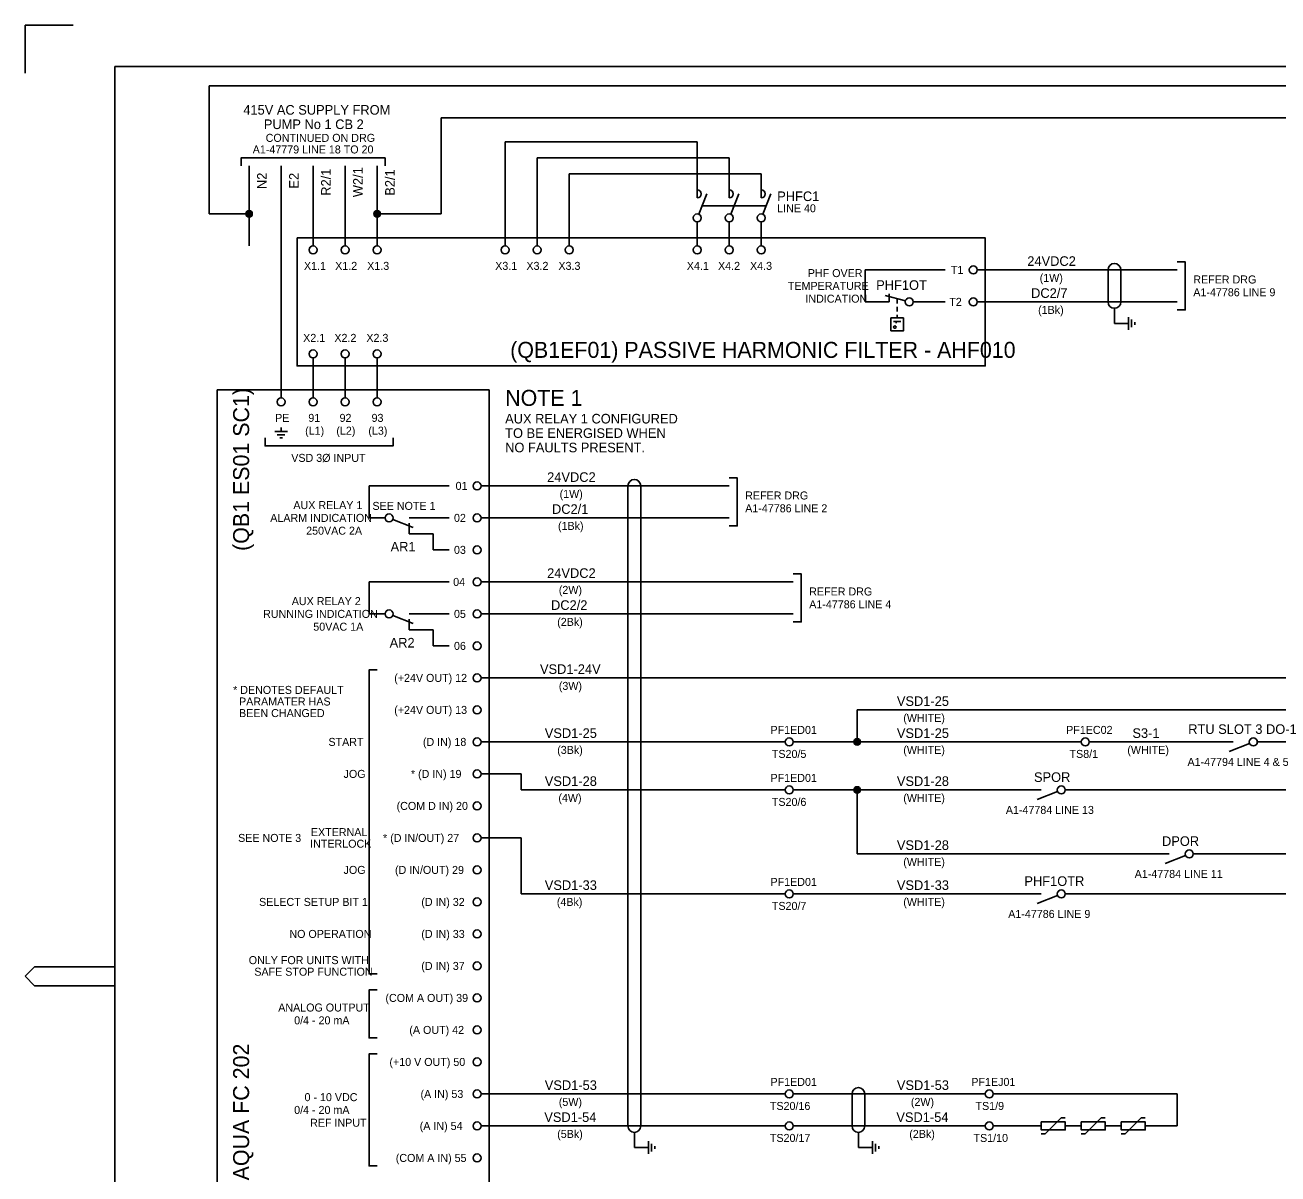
# Model space of a CAD drawing. Extents: x 0 to 841, y 0 to 594.
# Drawn here: x 0 to 391.4, y 235 to 594 of the extents above; entities that cross this region are included whole.
import ezdxf

# ---------------------------------------------------------------- set-up
doc = ezdxf.new("R2010")
doc.units = 0
for name, color, linetype in [('A1BORDER', 7, 'Continuous'), ('BASE', 7, 'Continuous'), ('Level 1', 7, 'Continuous'), ('Level 10', 7, 'Continuous'), ('Level 4', 7, 'Continuous'), ('Level 5', 7, 'Continuous'), ('Level 6', 7, 'Continuous')]:
    doc.layers.add(name, color=color, linetype=linetype)

msp = doc.modelspace()

# ---------------------------------------------------------------- linework, layer by layer
at = {"layer": 'A1BORDER'}
for p, q in [((0, 594), (15, 594)), ((0, 579), (0, 594)), ((28, 581), (829, 581)), ((28, 581), (28, 15)), ((3, 299.76), (0, 296.76)), ((28, 299.76), (3, 299.76)), ((3, 293.76), (0, 296.76)), ((28, 293.76), (3, 293.76))]:
    msp.add_line(p, q, dxfattribs=at)
at = {"layer": 'BASE'}
for p, q in [((338.37, 517.5), (338.37, 507.5)), ((342.37, 517.5), (342.37, 507.5)), ((340.37, 505.5), (340.37, 500.75)), ((344.74, 500.75), (340.37, 500.75)), ((188.37, 450), (188.37, 250)), ((192.37, 450), (192.37, 250)), ((258.37, 260), (258.37, 250)), ((262.37, 260), (262.37, 250)), ((190.37, 248), (190.37, 243.25)), ((260.37, 248), (260.37, 243.25)), ((194.74, 243.25), (190.37, 243.25)), ((264.74, 243.25), (260.37, 243.25))]:
    msp.add_line(p, q, dxfattribs=at)
for centre, start, end in [((340.37, 517.5), 0, 180), ((340.37, 507.5), 180, 0), ((190.37, 450), 0, 180), ((260.37, 260), 0, 180), ((190.37, 250), 180, 0), ((260.37, 250), 180, 0)]:
    msp.add_arc(centre, 2, start, end, dxfattribs=at)
at = {"layer": 'Level 1'}
for p, q in [((57.51, 535), (57.5, 575)), ((57.5, 575), (700, 575)), ((130, 535), (130, 565)), ((130, 565), (430, 565)), ((150, 557.5), (150, 525)), ((150, 557.5), (210, 557.5)), ((160, 552.5), (160, 525)), ((160, 552.5), (220, 552.5)), ((90, 550), (90, 525)), ((100, 550), (100, 525)), ((110, 525), (110, 550)), ((170, 525), (170, 547.5)), ((170, 547.5), (230, 547.5)), ((210, 540), (210, 542.5)), ((210.46, 534.91), (213, 541.25)), ((220, 540), (220, 542.5)), ((220.46, 534.91), (223, 541.25)), ((230, 540), (230, 542.5)), ((230.46, 534.91), (233, 541.25)), ((211.5, 537.5), (231.5, 537.5)), ((70, 535), (57.51, 535)), ((110, 535), (130, 535)), ((210, 532.5), (210, 525)), ((220, 532.5), (220, 525)), ((230, 525), (230, 532.5)), ((262.5, 517.5), (262.5, 507.5)), ((287.5, 517.5), (262.5, 517.5)), ((262.5, 507.5), (267.5, 507.5)), ((270, 507.5), (267.5, 507.5)), ((267.5, 507.5), (267.5, 507.5)), ((272.5, 508.5), (272.5, 507)), ((272.5, 506), (272.5, 504.5)), ((277.5, 507.5), (287.5, 507.5)), ((277.5, 507.5), (277.5, 507.5)), ((272.5, 503.5), (272.5, 502.5)), ((90, 490), (90, 477.5)), ((100, 490), (100, 477.5)), ((110, 477.5), (110, 490)), ((80, 467), (80, 468.25)), ((132.5, 450), (107.5, 450)), ((107.5, 450), (107.5, 440)), ((107.5, 440), (112.5, 440)), ((112.5, 440), (112.5, 440)), ((122.5, 440), (122.5, 440)), ((122.5, 440), (132.5, 440)), ((122.5, 435), (127.5, 435)), ((127.5, 435), (127.5, 430)), ((127.5, 430), (132.5, 430)), ((132.5, 420), (107.5, 420)), ((107.5, 420), (107.5, 410)), ((107.5, 410), (112.5, 410)), ((112.5, 410), (112.5, 410)), ((122.5, 410), (122.5, 410)), ((122.5, 410), (132.5, 410)), ((122.5, 405), (127.5, 405)), ((127.5, 405), (127.5, 400)), ((127.5, 400), (132.5, 400)), ((260, 370), (260, 380)), ((375, 370), (332.5, 370)), ((377.5, 370), (375, 370)), ((375, 370), (375, 370)), ((427.5, 370), (385, 370)), ((385, 370), (385, 370)), ((142.5, 360), (155, 360)), ((155, 360), (155, 355)), ((260, 355), (260, 335)), ((317.5, 355), (315, 355)), ((142.5, 340), (155, 340)), ((155, 340), (155, 322.5)), ((357.5, 335), (355, 335)), ((315, 322.5), (240, 322.5)), ((317.5, 322.5), (315, 322.5)), ((600, 322.5), (325, 322.5)), ((300, 260), (240, 260)), ((360, 260), (302.5, 260)), ((360, 260), (360, 250)), ((318.75, 247.5), (323.75, 252.5)), ((323.75, 252.5), (325, 252.5)), ((331.25, 247.5), (336.25, 252.5)), ((336.25, 252.5), (337.5, 252.5)), ((343.75, 247.5), (348.75, 252.5)), ((348.75, 252.5), (350, 252.5)), ((300, 250), (240, 250)), ((317.5, 250), (302.5, 250)), ((318.75, 247.5), (317.5, 247.5)), ((325, 250), (330, 250)), ((331.25, 247.5), (330, 247.5)), ((337.5, 250), (342.5, 250)), ((343.75, 247.5), (342.5, 247.5)), ((350, 250), (360, 250))]:
    msp.add_line(p, q, dxfattribs=at)
for points in [[(67.5, 550), (67.5, 552.5), (112.5, 552.5), (112.5, 550)], [(360, 520), (362.5, 520), (362.5, 505), (360, 505)], [(271.37, 501.37), (273.63, 501.37)], [(272.12, 501.62), (272.12, 500.87)], [(272.12, 499.64), (272.08, 499.82), (271.94, 499.95), (271.74, 500.01), (271.56, 499.95), (271.43, 499.82), (271.37, 499.64), (271.43, 499.44), (271.56, 499.3), (271.74, 499.26), (271.94, 499.3), (272.08, 499.44), (272.12, 499.64)], [(75, 465), (75, 462.5), (115, 462.5), (115, 465)], [(220, 452.5), (222.5, 452.5), (222.5, 437.5), (220, 437.5)], [(240, 422.5), (242.5, 422.5), (242.5, 407.5), (240, 407.5)], [(110, 297.5), (107.5, 297.5), (107.5, 392.5), (110, 392.5)], [(110, 277.5), (107.5, 277.5), (107.5, 292.5), (110, 292.5)], [(110, 237.5), (107.5, 237.5), (107.5, 272.5), (110, 272.5)]]:
    msp.add_lwpolyline(points, dxfattribs=at)
for points in [[(85, 527.5), (300, 527.5), (300, 487.5), (85, 487.5)], [(274.5, 502.5), (274.5, 498.5), (270.5, 498.5), (270.5, 502.5)], [(60, 480), (145, 480), (145, 160), (60, 160)]]:
    msp.add_lwpolyline(points, close=True, dxfattribs=at)
for centre in [(210, 533.75), (220, 533.75), (230, 533.75)]:
    msp.add_circle(centre, 1.25, dxfattribs=at)
for centre in [(210, 541.25), (220, 541.25), (230, 541.25)]:
    msp.add_arc(centre, 1.25, 270, 90, dxfattribs=at)
at = {"layer": 'Level 10'}
for p, q in [((69, 535), (69, 535)), ((69.1, 534.56), (69.1, 535.44)), ((69.4, 534.2), (69.4, 535.8)), ((69.7, 534.05), (69.7, 535.95)), ((70, 534), (70, 535.99)), ((70.3, 534.05), (70.3, 535.95)), ((70.6, 534.2), (70.6, 535.8)), ((70.9, 534.56), (70.9, 535.44)), ((109, 535), (109, 535)), ((109.1, 534.56), (109.1, 535.44)), ((109.4, 534.2), (109.4, 535.8)), ((109.7, 534.05), (109.7, 535.95)), ((110, 534), (110, 535.99)), ((110.3, 534.05), (110.3, 535.95)), ((110.6, 534.2), (110.6, 535.8)), ((110.9, 534.56), (110.9, 535.44)), ((275.04, 507.82), (268.75, 509.5)), ((270, 510), (270, 507.5)), ((344.74, 498.75), (344.74, 502.75)), ((345.74, 499.55), (345.74, 501.95)), ((346.74, 500.35), (346.74, 501.15)), ((78, 467), (82, 467)), ((78.8, 466), (81.2, 466)), ((79.6, 465), (80.4, 465)), ((114.91, 439.54), (121.25, 437)), ((120, 440), (122.5, 440)), ((120, 438.37), (120, 435)), ((120, 435), (122.5, 435)), ((114.91, 409.54), (121.25, 407)), ((120, 410), (122.5, 410)), ((120, 408.37), (120, 405)), ((120, 405), (122.5, 405)), ((259, 370), (259, 370)), ((259.1, 369.56), (259.1, 370.44)), ((259.4, 369.2), (259.4, 370.8)), ((259.7, 369.05), (259.7, 370.95)), ((260, 369), (260, 370.99)), ((260.3, 369.05), (260.3, 370.95)), ((260.6, 369.2), (260.6, 370.8)), ((260.9, 369.56), (260.9, 370.44)), ((382.59, 369.54), (376.25, 367)), ((259, 355), (259, 355)), ((259.1, 354.56), (259.1, 355.44)), ((259.4, 354.2), (259.4, 355.8)), ((259.7, 354.05), (259.7, 355.95)), ((260, 354), (260, 355.99)), ((260.3, 354.05), (260.3, 355.95)), ((260.6, 354.2), (260.6, 355.8)), ((260.9, 354.56), (260.9, 355.44)), ((322.59, 354.54), (316.25, 352)), ((362.59, 334.54), (356.25, 332)), ((322.59, 322.04), (316.25, 319.5)), ((194.74, 241.25), (194.74, 245.25)), ((195.74, 242.05), (195.74, 244.45)), ((196.74, 242.85), (196.74, 243.65)), ((264.74, 241.25), (264.74, 245.25)), ((265.74, 242.05), (265.74, 244.45)), ((266.74, 242.85), (266.74, 243.65))]:
    msp.add_line(p, q, dxfattribs=at)
for points in [[(317.5, 250), (317.5, 248.75), (325, 248.75), (325, 251.25), (317.5, 251.25), (317.5, 250)], [(330, 250), (330, 248.75), (337.5, 248.75), (337.5, 251.25), (330, 251.25), (330, 250)], [(342.5, 250), (342.5, 248.75), (350, 248.75), (350, 251.25), (342.5, 251.25), (342.5, 250)]]:
    msp.add_lwpolyline(points, dxfattribs=at)
for centre, radius in [((70, 535), 1), ((110, 535), 1), ((276.25, 507.5), 1.25), ((113.75, 440), 1.25), ((113.75, 410), 1.25), ((260, 370), 1), ((383.75, 370), 1.25), ((323.75, 355), 1.25), ((260, 355), 1), ((363.75, 335), 1.25), ((323.75, 322.5), 1.25)]:
    msp.add_circle(centre, radius, dxfattribs=at)
at = {"layer": 'Level 4'}
for centre in [(90, 523.75), (100, 523.75), (110, 523.75), (150, 523.75), (160, 523.75), (170, 523.75), (210, 523.75), (220, 523.75), (230, 523.75), (90, 491.25), (100, 491.25), (110, 491.25), (80, 476.25), (90, 476.25), (100, 476.25), (110, 476.25)]:
    msp.add_circle(centre, 1.25, dxfattribs=at)
at = {"layer": 'Level 5'}
for p, q in [((210, 557.5), (210, 542.5)), ((220, 552.5), (220, 542.5)), ((70, 550), (70, 525)), ((80, 550), (80, 477.5)), ((230, 547.5), (230, 542.5))]:
    msp.add_line(p, q, dxfattribs=at)
for centre in [(296.25, 517.5), (296.25, 507.5), (141.25, 450), (141.25, 440), (141.25, 430), (141.25, 420), (141.25, 410), (141.25, 400), (141.25, 390), (141.25, 380), (141.25, 370), (238.75, 370), (331.25, 370), (141.25, 360), (238.75, 355), (141.25, 350), (141.25, 340), (141.25, 330), (141.25, 320), (238.75, 322.5), (141.25, 310), (141.25, 300), (141.25, 290), (141.25, 280), (141.25, 270), (141.25, 260), (238.75, 260), (301.25, 260), (141.25, 250), (238.75, 250), (301.25, 250), (141.25, 240)]:
    msp.add_circle(centre, 1.25, dxfattribs=at)
at = {"layer": 'Level 6'}
for p, q in [((297.5, 517.5), (360, 517.5)), ((297.5, 507.5), (360, 507.5)), ((142.5, 450), (220, 450)), ((142.5, 440), (220, 440)), ((142.5, 420), (240, 420)), ((142.5, 410), (240, 410)), ((142.5, 390), (601.25, 390)), ((260, 380), (520, 380)), ((142.5, 370), (237.5, 370)), ((240, 370), (330, 370)), ((155, 355), (237.5, 355)), ((240, 355), (315, 355)), ((325, 355), (435, 355)), ((260, 335), (355, 335)), ((365, 335), (420, 335)), ((155, 322.5), (237.5, 322.5)), ((142.5, 260), (237.5, 260)), ((142.5, 250), (237.5, 250))]:
    msp.add_line(p, q, dxfattribs=at)

# ---------------------------------------------------------------- texts
at = {"layer": 'Level 1'}
for s, height, p in [('CONTINUED ON DRG', 2.5, (75.18, 557.5)), (' A1-47779 LINE 18 TO 20', 2.5, (70.2, 553.88)), ('PHFC1', 3, (235, 539)), ('LINE 40', 2.5, (235, 535.5)), ('X1.1', 2.5, (87.14, 517.5)), ('X1.2', 2.5, (96.89, 517.5)), ('X1.3', 2.5, (106.89, 517.5)), ('X3.1', 2.5, (146.89, 517.5)), ('X3.2', 2.5, (156.64, 517.5)), ('X3.3', 2.5, (166.64, 517.5)), ('X4.1', 2.5, (206.76, 517.5)), ('X4.2', 2.5, (216.51, 517.5)), ('X4.3', 2.5, (226.51, 517.5)), ('PHF OVER', 2.5, (244.56, 515.25)), ('T1', 2.5, (289.26, 516.25)), ('TEMPERATURE', 2.5, (238.33, 511.25)), ('REFER DRG', 2.5, (365, 513.25)), ('INDICATION', 2.5, (243.81, 507.25)), ('A1-47786 LINE 9', 2.5, (365, 509.25)), ('T2', 2.5, (288.76, 506.25)), ('X2.1', 2.5, (86.89, 495)), ('X2.2', 2.5, (96.64, 495)), ('X2.3', 2.5, (106.64, 495)), ('(QB1EF01) PASSIVE HARMONIC FILTER - AHF010', 5, (151.57, 490)), ('NOTE 1', 5, (150, 475)), ('PE', 2.5, (78.13, 470)), ('91', 2.5, (88.5, 470)), ('92', 2.5, (98.26, 470)), ('93', 2.5, (108.26, 470)), ('AUX RELAY 1 CONFIGURED', 3, (150, 469.5)), ('(L1)', 2.5, (87.51, 465.99)), ('(L2)', 2.5, (97.26, 465.99)), ('(L3)', 2.5, (107.26, 465.99)), ('TO BE ENERGISED WHEN', 3, (150, 465)), ('NO FAULTS PRESENT.', 3, (150, 460.5)), ('VSD 3Ø INPUT', 2.5, (83.17, 457.5)), ('01', 2.5, (134.51, 448.75)), ('REFER DRG', 2.5, (225, 445.75)), ('AUX RELAY 1', 2.5, (83.83, 442.75)), ('SEE NOTE 1', 2.5, (108.54, 442.5)), ('A1-47786 LINE 2', 2.5, (225, 441.75)), ('ALARM INDICATION', 2.5, (76.61, 438.75)), ('02', 2.5, (134.01, 438.75)), ('250VAC 2A', 2.5, (87.82, 434.75)), ('03', 2.5, (134.01, 428.75)), ('04', 2.5, (133.76, 418.75)), ('AUX RELAY 2', 2.5, (83.33, 412.75)), ('REFER DRG', 2.5, (245, 415.75)), ('RUNNING INDICATION', 2.5, (74.37, 408.75)), ('05', 2.5, (134.01, 408.75)), ('A1-47786 LINE 4', 2.5, (245, 411.75)), ('50VAC 1A', 2.5, (90.06, 404.75)), ('06', 2.5, (134.01, 398.75)), ('* DENOTES DEFAULT', 2.5, (65, 385)), ('(+24V OUT) 12', 2.5, (115.34, 388.75)), ('  PARAMATER HAS', 2.5, (65, 381.38)), ('  BEEN CHANGED', 2.5, (65, 377.76)), ('(+24V OUT) 13', 2.5, (115.34, 378.75)), ('PF1ED01', 2.5, (232.9, 372.5)), ('PF1EC02', 2.5, (325.27, 372.5)), ('START', 2.5, (94.79, 368.75)), ('(D IN) 18', 2.5, (124.3, 368.75)), ('JOG', 2.5, (99.52, 358.75)), ('* (D IN) 19', 2.5, (120.56, 358.75)), ('PF1ED01', 2.5, (232.9, 357.5)), ('(COM D IN) 20', 2.5, (116.08, 348.75)), ('SEE NOTE 3', 2.5, (66.57, 338.75)), ('EXTERNAL', 2.5, (89.31, 340.56)), ('* (D IN/OUT) 27', 2.5, (111.85, 338.75)), ('INTERLOCK', 2.5, (89.07, 336.94)), ('JOG', 2.5, (99.52, 328.75)), ('(D IN/OUT) 29', 2.5, (115.58, 328.75)), ('PF1ED01', 2.5, (232.9, 325)), ('SELECT SETUP BIT 1', 2.5, (73.12, 318.75)), ('(D IN) 32', 2.5, (123.8, 318.75)), ('NO OPERATION', 2.5, (82.59, 308.75)), ('(D IN) 33', 2.5, (123.8, 308.75)), ('ONLY FOR UNITS WITH', 2.5, (69.89, 300.56)), ('SAFE STOP FUNCTION', 2.5, (71.63, 296.94)), ('(D IN) 37', 2.5, (123.8, 298.75)), ('(COM A OUT) 39', 2.5, (112.6, 288.75)), ('ANALOG OUTPUT', 2.5, (79.1, 285.75)), ('0/4 - 20 mA', 2.5, (84.08, 281.75)), ('(A OUT) 42', 2.5, (120.07, 278.75)), ('(+10 V OUT) 50', 2.5, (113.84, 268.75)), ('PF1ED01', 2.5, (232.9, 262.5)), ('PF1EJ01', 2.5, (295.65, 262.5)), ('0 - 10 VDC', 2.5, (87.32, 257.75)), ('(A IN) 53', 2.5, (123.55, 258.75)), ('0/4 - 20 mA', 2.5, (84.08, 253.75)), ('REF INPUT', 2.5, (89.06, 249.75)), ('(A IN) 54', 2.5, (123.31, 248.75)), ('(COM A IN) 55', 2.5, (115.83, 238.75))]:
    msp.add_text(s, height=height, dxfattribs=at).set_placement(p)
for s, height, p in [('R2/1', 3, (95.5, 540.67)), ('W2/1', 3, (105.5, 540.22)), ('B2/1', 3, (115.5, 540.67)), ('N2', 3, (75.5, 542.76)), ('E2', 3, (85.5, 542.91)), ('(QB1 ES01 SC1)', 5, (70, 429.68)), ('VSD - DANFOSS VLT AQUA FC 202', 5, (70, 165))]:
    msp.add_text(s, height=height, rotation=90, dxfattribs=at).set_placement(p)
at = {"layer": 'Level 5'}
for s, height, p in [('415V AC SUPPLY FROM', 3, (68.19, 566)), ('PUMP No 1 CB 2', 3, (74.61, 561.5)), ('24VDC2', 3, (313.13, 518.75)), ('PHF1OT', 3, (265.93, 511.25)), ('(1W)', 2.5, (317.01, 513.75)), ('DC2/7', 3, (314.32, 508.75)), ('(1Bk)', 2.5, (316.51, 503.75)), ('24VDC2', 3, (163.12, 451.25)), ('(1W)', 2.5, (167.01, 446.25)), ('DC2/1', 3, (164.63, 441.25)), ('(1Bk)', 2.5, (166.51, 436.25)), ('AR1', 3, (114.21, 429.5)), ('24VDC2', 3, (163.12, 421.25)), ('(2W)', 2.5, (166.76, 416.25)), ('DC2/2', 3, (164.33, 411.25)), ('(2Bk)', 2.5, (166.26, 406.25)), ('AR2', 3, (113.91, 399.5)), ('VSD1-24V', 3, (160.88, 391.25)), ('(3W)', 2.5, (166.76, 386.25)), ('VSD1-25', 3, (272.38, 381.25)), ('(WHITE)', 2.5, (274.39, 376.25)), ('VSD1-25', 3, (162.38, 371.25)), ('VSD1-25', 3, (272.38, 371.25)), ('S3-1', 3, (345.97, 371.25)), ('RTU SLOT 3 DO-1', 3, (363.42, 372.5)), ('(3Bk)', 2.5, (166.26, 366.25)), ('(WHITE)', 2.5, (274.39, 366.25)), ('(WHITE)', 2.5, (344.39, 366.25)), ('TS20/5', 2.5, (233.33, 365)), ('TS8/1', 2.5, (326.33, 365)), ('A1-47794 LINE 4 & 5', 2.5, (363.19, 362.5)), ('SPOR', 3, (315.22, 357.5)), ('VSD1-28', 3, (162.38, 356.25)), ('VSD1-28', 3, (272.38, 356.25)), ('(4W)', 2.5, (166.63, 351.25)), ('TS20/6', 2.5, (233.33, 350)), ('(WHITE)', 2.5, (274.39, 351.25)), ('A1-47784 LINE 13', 2.5, (306.43, 347.5)), ('VSD1-28', 3, (272.38, 336.25)), ('DPOR', 3, (355.22, 337.5)), ('(WHITE)', 2.5, (274.39, 331.25)), ('A1-47784 LINE 11', 2.5, (346.68, 327.5)), ('VSD1-33', 3, (162.38, 323.75)), ('VSD1-33', 3, (272.38, 323.75)), ('PHF1OTR', 3, (312.23, 325)), ('(4Bk)', 2.5, (166.14, 318.75)), ('(WHITE)', 2.5, (274.39, 318.75)), ('TS20/7', 2.5, (233.33, 317.5)), ('A1-47786 LINE 9', 2.5, (307.18, 315)), ('VSD1-53', 3, (162.38, 261.25)), ('VSD1-53', 3, (272.38, 261.25)), ('(5W)', 2.5, (166.76, 256.25)), ('(2W)', 2.5, (276.76, 256.25)), ('TS20/16', 2.5, (232.71, 255)), ('TS1/9', 2.5, (296.95, 255)), ('VSD1-54', 3, (162.23, 251.25)), ('VSD1-54', 3, (272.23, 251.25)), ('(5Bk)', 2.5, (166.26, 246.25)), ('TS20/17', 2.5, (232.71, 245)), ('(2Bk)', 2.5, (276.26, 246.25)), ('TS1/10', 2.5, (296.33, 245))]:
    msp.add_text(s, height=height, dxfattribs=at).set_placement(p)

doc.saveas('drawing.dxf')
